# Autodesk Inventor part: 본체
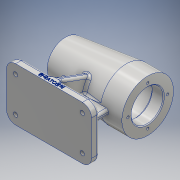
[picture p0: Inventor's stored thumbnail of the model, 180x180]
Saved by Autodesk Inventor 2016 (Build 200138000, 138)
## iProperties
Created: 2018-09
Part Number: 본체
Material: 알루미늄 6061
Document SubType Name: Modeling
Designer: CAMTIC
Density: 2.7 g/cm^3
Appearance: 알루미늄 - 평지
Author: CAMTIC
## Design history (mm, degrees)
sketch "스케치1"
  geometry: L1 (56, 35)-(-56, 35); L2 (-56, 35)-(-56, -35); L3 (-56, -35)-(56, -35); L4 (56, -35)-(56, 35); L5 (56, 35)-(-56, -35); L6 (-56, 35)-(56, -35); 1 further point
  constraints: 12 end point, 2 midpoint, 2 parallel, 1 horizontal, 1 perpendicular
  dimensions: "d0" = 112 distance of L3.end L2.end; "d1" = 70 distance of L2.end L1.end
extrude "돌출1" new body sketch "스케치1" distance "d2" = 10; taper "d3" = 0 deg
sketch "스케치3"
  geometry: L1 (56, 74)-(-56, 74); L2 (56, 74)-(56, 108); L3 (56, 108)-(28, 108); L4 (28, 108)-(-52.27, 98.144); L5 (56, 0)-(56, 10) reference; L6 (-56, 0)-(56, 0) reference; L7 (-56, 10)-(56, 10) reference; A1 r 80 centre (24, 74) between (-52.27, 98.144) and (-56, 74); 1 further point
  constraints: 8 end point, 2 horizontal, 2 point on circle, 1 centre point, 1 collinear, 1 parallel, 1 point on line, 1 vertical
  dimensions: "d4" = 112 distance of L1.start L1.end; "d5" = 34 distance of L1.start L2.end; "d6" = 28 distance of L2.end L3.end; "d7" = 173 deg angle of L4 L3; "d8" = 160 diameter of A1; "d9" = 74 distance between parallel lines of L6 L1
revolve "회전1" sketch "스케치3" stored, may be unused: angle "d10" = 90 deg
sketch "스케치4"
  geometry: L1 (-4, 35)-(-4, 4); L2 (-4, 4)-(-38, 4); L3 (-38, 4)-(-38, -4); L4 (-38, -4)-(-4, -4); L5 (-4, -4)-(-4, -35); L6 (-4, -35)-(4, -35); L7 (4, -35)-(4, -4); L8 (4, -4)-(38, -4); L9 (38, -4)-(38, 4); L10 (38, 4)-(4, 4); L11 (4, 35)-(-4, 35); L12 (4, 35)-(4, 4); L13 (0, 49)-(0, -49) reference; L14 (78.4, 0)-(-78.4, 0) reference; L15 (-56, 35)-(-56, -35) reference; L16 (56, -35)-(56, 35) reference; L17 (56, 35)-(-56, 35) reference; L18 (-56, -35)-(56, -35) reference; L19 (-4, 4)-(4, 4); L20 (-4, -4)-(4, -4); 1 further point
  constraints: 28 end point, 8 perpendicular, 8 point on line, 2 collinear, 2 parallel, 1 vertical
  dimensions: "d11" = 8 distance of L11.start L1.start; "d12" = 8 distance of L8.end L9.end; "d13" = 4 distance between parallel lines of L13 L1; "d14" = 4 distance between parallel lines of L8 L14; "d15" = 18 distance between parallel lines of L3 L15; "d16" = 18 distance between parallel lines of L9 L16
extrude "돌출2" join sketch "스케치4" stored distance "d17" = 10; taper "d18" = 0 deg
feature "면 기울기1" dims angle "d23" = 15 deg
sketch "스케치5"
  geometry: C1 r 21 at (0, 0); 1 further point
  constraints: 1 centre point
  dimensions: "d25" = 42 diameter of C1
extrude "돌출5" cut sketch "스케치5" distance "d26" = 15; taper "d27" = 0 deg
sketch "스케치6"
  geometry: C1 r 24 at (0, 0); 1 further point
  constraints: 1 centre point
  dimensions: "d28" = 48 diameter of C1
extrude "돌출6" cut sketch "스케치6" distance "d29" = 54; taper "d30" = 0 deg
sketch "스케치7"
  geometry: C1 r 21 at (0, 0); 1 further point
  constraints: 1 centre point
  dimensions: "d31" = 42 diameter of C1
extrude "돌출7" cut sketch "스케치7" distance "d32" = 12; taper "d33" = 0 deg
sketch "스케치8"
  geometry: C1 r 17.5 at (0, 0); 1 further point
  constraints: 1 centre point
  dimensions: "d34" = 35 diameter of C1
extrude "돌출8" cut sketch "스케치8" distance "d35" = 18; taper "d36" = 0 deg
sketch "스케치9"
  geometry: C1 r 16 at (0, 0); 1 further point
  constraints: 1 centre point
  dimensions: "d37" = 32 diameter of C1
extrude "돌출9" cut sketch "스케치9" distance "d38" = 4; taper "d39" = 0 deg
sketch "스케치10"
  geometry: C1 r 10.5 at (0, 0); 1 further point
  constraints: 1 centre point
  dimensions: "d40" = 21 diameter of C1
extrude "돌출10" cut sketch "스케치10" distance "d41" = 3; taper "d42" = 0 deg
sketch "스케치12"
  geometry: A1 r 26 centre (0, 0) between (0, 26) and (-26, 0); 3 further points
  constraints: 4 point on circle, 1 centre point
  dimensions: "d47" = 52 diameter of A1
hole "구멍1" sketch "스케치12" at (0, 26), (-26, 0), (0, -26), (26, 0) diameter "d48" = 3.242; stored, may be unused: countersink angle "d52" = 90 deg, drill point angle "d54" = 118 deg; dims "d49" = 8, "d50" = 4, "d51" = 2, "d53" = 11
fillet "모깎기10" dims "d69" = 12
sketch "스케치11"
  geometry: L1 (10, 35)-(56.444, 18.096); L2 (10, 35)-(59.424, 35); L3 (56.444, 18.096)-(56.444, -18.096); L4 (0, 23)-(0, 35) reference; L5 (10, 35)-(10, 23) reference; L6 (10, -23)-(10, -35) reference; L7 (10, 35)-(10, -35); L8 (10, -35)-(56.444, -18.096); 2 further points
  constraints: 10 end point, 2 coincident, 1 collinear, 1 equal length, 1 horizontal, 1 parallel
  dimensions: "d79" = 20 deg angle of L1 L2; "d80" = 70 deg angle of L8 L7
extrude "돌출11" join sketch "스케치11" stored distance "d44" = 8; taper "d45" = 0 deg
fillet "모깎기1" dims "d55" = 3, "d56" = 0.3
chamfer "모따기1" distance "d57" = 1; stored, may be unused: second distance "d58" = 2, angle "d59" = 45 deg
hole "구멍3" diameter "d98" = 5.5; stored, may be unused: countersink angle "d102" = 90 deg, drill point angle "d104" = 118 deg; dims "d96" = 10, "d97" = 10, "d99" = 8, "d100" = 9.5, "d101" = 5.4, "d103" = 11
fillet "모깎기24" dims "d105" = 3
fillet "모깎기28" dims "d109" = 3
fillet "모깎기29" dims "d110" = 3
fillet "모깎기30" dims "d111" = 3
fillet "모깎기31" dims "d112" = 3
fillet "모깎기32" dims "d113" = 3
sketch "스케치13"
  geometry: L1 (26.849, 6.316)-(60.032, 6.316); L2 (60.032, 6.316)-(60.032, 1.513); L3 (60.032, 1.513)-(26.849, 1.513); L4 (26.849, 1.513)-(26.849, 6.316); 1 further point
  constraints: 2 other
feature "엠보싱1" sketch "스케치13" dims "d0" = 112, "d1" = 70, "d114" = 0.5, "d115" = 0
node "솔리드1"
mirror "대칭3"
mirror "대칭4"
